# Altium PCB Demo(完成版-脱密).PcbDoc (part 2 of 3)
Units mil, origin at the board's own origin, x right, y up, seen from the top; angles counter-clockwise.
Board outline 2165.35 x 1574.8 mil, 6 copper layers (TOP, GND02, ART03, ART04, PWR05, BOTTOM); 172 components, 0 nets, 834 pads, 541 vias.
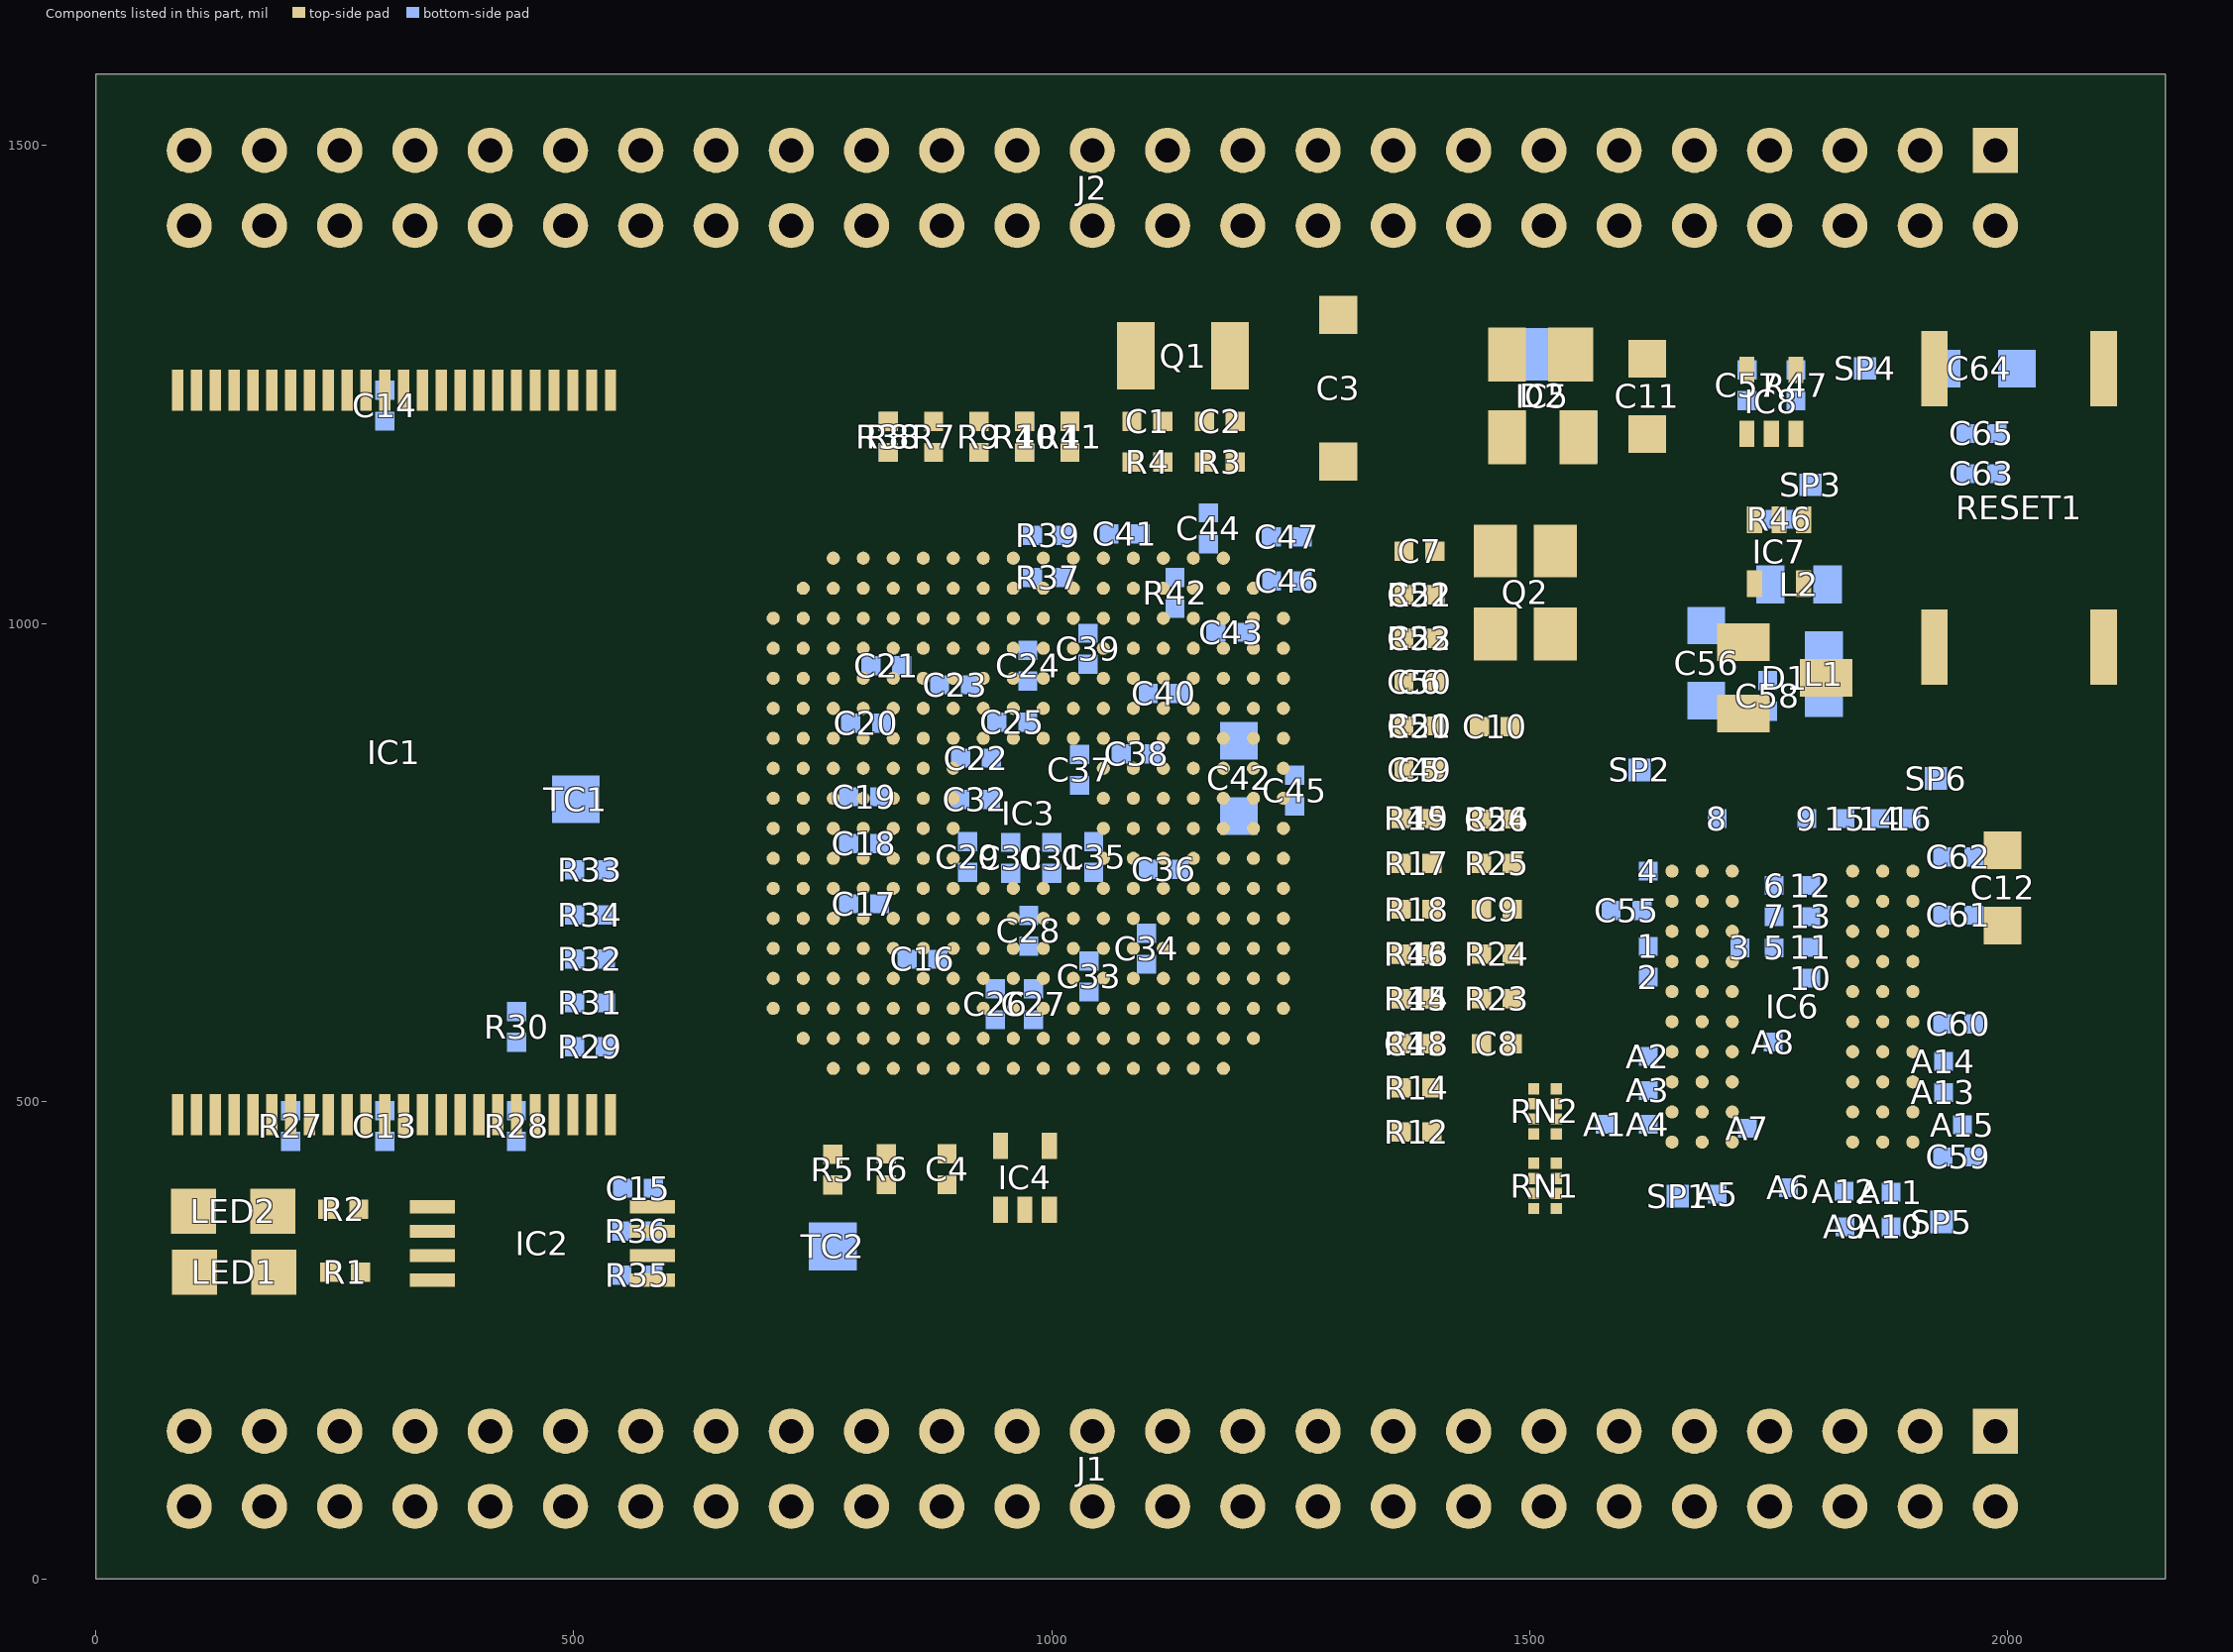
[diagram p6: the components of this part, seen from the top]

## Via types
v1: diameter 16, hole 8, TOP to BOTTOM, tented both sides, 541 vias

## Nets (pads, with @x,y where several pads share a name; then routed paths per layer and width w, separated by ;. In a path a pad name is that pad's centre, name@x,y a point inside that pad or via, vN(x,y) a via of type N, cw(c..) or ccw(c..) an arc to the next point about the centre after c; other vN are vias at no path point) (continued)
copper on no net: | length 160065.2
  TOP w5: v1(1330,664) 1337.48,671.48 1348.13,671.48 1365.56,654.06 ; v1(1330,693) 1330.48,693 1340,683.48 1348.13,683.48 1365.56,700.91 ; 1397.84,654.06 1412.79,669 v1(1423,669) ; v1(1423,700.91) 1449.56,700.91 1449.56,654.06 1449.56,607.2 1449.56,560.34
  TOP w5.7: v1(125.01,1073.73) 265.01,1073.73 400.58,1209.3 400.58,1243.94 ; v1(126.01,1120.73) 164.37,1159.09 164.37,1243.94 ; 184.05,1243.94 184.05,1204.92 v1(184.1,1204.87) ; 194,382 199,387 ; 196,326 201,321 ; v1(203.69,555.14) 223.42,535.41 223.42,486.07 ; 203.73,486.07 203.73,525.09 v1(203.78,525.14) ; 203.74,1243.94 203.74,1140 v1(223.01,1120.73) ; 223.42,1243.94 223.42,1204.92 v1(223.47,1204.87) ; 243.1,486.07 243.1,547.82 v1(285.01,589.73) ; v1(315.01,1084.87) 333.87,1103.73 352.01,1103.73 439.96,1191.68 439.96,1243.94 ; v1(316.01,1048.73) 459.64,1192.36 459.64,1243.94 ; v1(350.32,1124.87) 420.27,1194.82 420.27,1243.94 ; v1(365.01,525.73) 376.01,525.73 380.9,520.84 380.9,486.07 ; 400.58,486.07 v1(400.63,525.14) v1(400.63,525.14) ; v1(411.01,426.73) 420.27,435.99 420.27,486.07 ; 439.95,486.07 v1(440,525.14) v1(440,525.14) ; 582.31,312.82 820.69,312.82 v1@821.18,312.33 ; 582.31,338.41 v1(818.15,338.41) v1@818.24,338.5 ; 582.31,364 625.82,364 v1(626,364.18) ; v1(598.7,926.9) 614.4,942.6 708.6,942.6 ; v1(630.1,644.3) 692.9,644.3 708.6,660 ; v1(630.1,707.1) 645.8,722.8 708.6,722.8 ; v1(630.1,926.9) 692.9,926.9 708.6,911.2 ; v1(661.5,707.1) 724.3,707.1 740,722.8 ; v1(661.5,769.9) 692.9,801.3 755.7,801.3 771.4,785.6 ; v1(661.5,864.1) 677.2,879.8 708.6,879.8 ; v1@692.9,455.9 771.4,534.4 ; v1(692.9,581.5) 708.6,597.2 ; v1(692.9,612.9) 755.7,612.9 771.4,628.6 ; v1(692.9,675.7) 708.6,691.4 ; v1(692.9,769.9) 708.6,754.2 ; v1(692.9,864.1) 708.6,848.4 ; v1(692.9,989.7) 708.6,974 ; v1(692.9,1021.1) 708.6,1005.4 ; v1(724.3,455.9) 767.13,498.73 794.01,498.73 802.8,507.52 802.8,534.4 ; v1(724.3,518.7) 771.4,565.8 ; v1(724.3,581.5) 740,597.2 ; v1(724.3,675.7) 740,691.4 ; v1(724.3,738.5) 740,754.2 ; v1(724.3,769.9) 740,785.6 ; v1(724.3,832.7) 740,817 ; v1(724.3,864.1) 740,848.4 ; v1(724.3,958.3) 740,942.6 ; v1(724.3,989.7) 740,974 ; v1(724.3,1115.3) 724.3,1021.1 740,1005.4 ; v1(755.7,581.5) 771.4,597.2 ; v1(755.7,644.3) 771.4,660 ; v1(755.7,675.7) 771.4,691.4 ; v1(755.7,738.5) 771.4,754.2 ; v1(755.7,832.7) 771.4,817 ; v1(755.7,864.1) 771.4,848.4 ; v1(755.7,895.5) 771.4,879.8 ; v1(755.7,958.3) 771.4,942.6 ; v1(755.7,989.7) 771.4,974 ; v1(755.7,1021.1) 771.4,1005.4 ; v1(755.7,1115.3) 755.7,1052.5 771.4,1036.8 ; v1@755.7,1146.7 771.4,1131 771.4,1068.2 ; v1(771,385.74) 771,412.32 ; 771,444.6 v1(803.12,444.6) ; 771.4,911.2 v1(787.1,926.9) ; v1(787.1,518.7) 787.1,550.1 802.8,565.8 ; v1(787.1,581.5) 802.8,597.2 ; v1(787.1,612.9) 802.8,628.6 ; v1(787.1,644.3) 802.8,660 ; v1(787.1,675.7) 802.8,691.4 ; v1(787.1,738.5) 802.8,754.2 ; v1(787.1,864.1) 802.8,879.8 ; v1(787.1,1021.1) 802.8,1005.4 ; v1(787.1,1115.3) 787.1,1052.5 802.8,1036.8 ; v1(787.1,1151) 802.8,1135.3 802.8,1131 802.8,1068.2 ; 802.8,785.6 818.5,801.3 v1(849.9,801.3) ; v1(818.5,550.1) 834.2,565.8 ; v1(818.5,581.5) 834.2,597.2 ; v1(818.5,612.9) 834.2,628.6 ; v1(818.5,644.3) 834.2,660 ; v1(818.5,675.7) 834.2,691.4 ; v1(818.5,864.1) 834.2,848.4 ; v1(818.5,926.9) 834.2,911.2 ; v1(818.5,1021.1) 834.2,1005.4 ; v1(818.5,1052.5) 834.2,1036.8 ; v1(818.5,1083.9) 834.2,1068.2 ; 827,445 v1(827.01,476.73) ; v1(829,1151) 829,1179 ; 834.2,534.4 865.6,503 v1(897,503) ; v1(849.9,550.1) 865.6,565.8 ; v1(849.9,581.5) 865.6,597.2 ; v1(849.9,612.9) 865.6,628.6 ; v1(849.9,1021.1) 865.6,1005.4 ; v1(849.9,1052.5) 865.6,1036.8 ; v1(849.9,1083.9) 865.6,1068.2 ; 865.6,534.4 881.3,518.7 912.7,518.7 v1(928.4,503) ; v1(876.5,1151) 876.5,1179 ; 876.5,1211.28 v1(876.5,1239.28) ; v1(881.3,550.1) 897,565.8 ; v1(881.3,581.5) 897,597.2 ; v1(881.3,612.9) 897,628.6 ; v1(881.3,895.5) 897,911.2 ; v1(881.3,958.3) 897,942.6 ; v1(881.3,989.7) 897,974 ; v1(881.3,1021.1) 897,1005.4 ; v1(881.3,1115.3) 881.3,1083.9 897,1068.2 ; v1(912.7,550.1) 928.4,565.8 ; v1(912.7,581.5) 928.4,597.2 ; v1(912.7,612.9) 928.4,628.6 ; v1(912.7,958.3) 928.4,942.6 ; v1(912.7,989.7) 928.4,974 ; v1(912.7,1083.9) 912.7,1052.5 928.4,1036.8 ; v1(924,1115.3) 924,1104 928.4,1099.6 928.4,1068.2 ; v1@924,1151 v1(924,1154) 924,1179 ; 924,1211.28 v1(924,1239.28) ; v1(944.1,958.3) 959.8,942.6 ; v1(944.1,989.7) 959.8,974 ; v1(944.1,1021.1) 959.8,1005.4 ; v1(944.1,1052.5) 959.8,1036.8 ; v1(944.1,1083.9) 959.8,1068.2 ; v1@971.5,1151 v1(971.5,1154) 971.5,1179 ; 991.2,942.6 v1(1006.9,958.3) ; 991.2,974 v1(1006.9,989.7) ; 991.2,1005.4 v1(1006.9,1021.1) ; v1(1006.9,612.9) 1022.6,628.6 ; v1@1019,1151 v1(1019,1154) 1019,1179 ; 1022.6,597.2 v1(1038.3,581.5) ; 1054,534.4 v1(1069.7,518.7) ; 1054,565.8 v1(1069.7,550.1) ; 1054,597.2 v1(1069.7,581.5) ; 1054,628.6 v1(1069.7,612.9) ; 1054,942.6 1069.7,958.3 v1(1069.7,989.7) ; 1054,1005.4 v1(1069.7,1021.1) ; v1(1069.7,1052.5) 1085.4,1036.8 ; 1083.86,1169 1083.86,1211.28 1088.15,1215.58 1088.15,1280 1088.15,1263.15 ; 1085.4,534.4 v1(1101.1,518.7) ; 1085.4,565.8 v1(1101.1,550.1) ; 1085.4,597.2 v1(1101.1,581.5) ; 1085.4,628.6 v1(1101.1,612.9) ; 1085.4,942.6 v1(1101.1,958.3) ; 1085.4,1005.4 v1(1101.1,1021.1) ; 1116.14,1169 1130,1155.14 1130,1128 1101.1,1099.1 1101.1,1052.5 1116.8,1036.8 ; 1116.8,534.4 v1(1132.5,518.7) ; 1116.8,565.8 v1(1132.5,550.1) ; 1116.8,597.2 v1(1132.5,581.5) ; 1116.8,628.6 v1(1132.5,612.9) ; 1116.8,1005.4 1132.5,1021.1 1132.5,1081.5 1148,1097 1148,1157.14 1159.86,1169 ; v1(1132.5,675.7) 1148.2,691.4 ; 1148.2,534.4 v1(1163.9,518.7) ; 1148.2,565.8 v1(1163.9,550.1) ; 1148.2,597.2 v1(1163.9,581.5) ; 1148.2,628.6 v1(1163.9,612.9) ; 1148.2,660 v1(1163.9,644.3) ; 1148.2,722.8 v1(1163.9,707.1) ; 1148.2,754.2 v1(1163.9,738.5) ; 1148.2,785.6 1163.9,801.3 v1@1336.01,801.3 ; 1148.2,911.2 v1(1163.9,926.9) ; 1148.2,942.6 v1(1163.9,958.3) ; 1148.2,974 1163.9,989.7 1362.97,989.7 1368.5,984.17 ; v1(1163.9,675.7) 1179.6,660 ; 1179.6,565.8 v1(1195.3,550.1) ; 1179.6,597.2 v1(1195.3,612.9) ; 1179.6,691.4 v1(1195.3,675.7) ; 1179.6,722.8 v1(1195.3,707.1) ; 1179.6,754.2 v1(1195.3,738.5) ; 1179.6,942.6 v1(1195.3,926.9) ; 1179.6,1036.8 1200.8,1058 1251,1058 1305,1004 1342.6,1004 1368.5,1029.9 ; 1186.58,1280 1192.14,1274.44 1192.14,1211.28 1192.14,1169.23 ; 1192.14,1169 1192.14,1169.23 ; 1211.01,597.2 1220.54,597.2 1242.42,575.32 1242.42,488.58 1263.12,467.88 1365.56,467.88 ; 1211.01,628.6 v1(1226.71,612.9) ; 1211.01,660 v1(1226.71,644.3) ; 1211.01,691.4 v1(1226.71,675.7) ; 1211.01,722.8 v1(1226.71,707.1) ; 1211.01,754.2 v1(1226.71,738.5) ; 1211.01,974 v1(1226.71,958.3) ; 1211.01,1005.4 v1(1226.71,1021.1) ; v1(1226.98,770.18) 1242.4,785.6 1242.68,785.88 ; 1242.4,597.2 v1(1258.1,581.5) ; 1242.4,628.6 1288.14,628.6 1296.01,620.73 1296.01,593.73 1292.01,589.73 1284.01,589.73 1278.01,595.73 1278.01,605.73 1270.84,612.9 v1(1258.1,612.9) ; 1242.4,660 v1(1258.1,644.3) ; 1242.4,691.4 v1(1258.1,675.7) ; 1242.4,722.8 v1(1258.1,707.1) ; 1242.4,754.2 1276.55,720.05 1276.55,673.19 1315.01,634.73 1315.01,540.99 1342.12,513.88 1365.56,513.88 ; 1242.4,1005.4 v1(1258.1,1021.1) ; 1300,1169.23 1192.14,1169.23 ; v1(1339,893) 1339.28,892.72 1368.5,892.72 1368.5,847 ; 1365.56,560.34 1365.56,607.2 ; 1365.56,748.97 1365.56,795.83 ; 1397.84,467.88 1427.39,497.43 v1(1427.39,514.01) ; 1397.84,513.88 1397.84,560.34 v1(1397.84,583.73) ; 1397.84,607.2 v1(1420.88,630.24) ; 1397.84,700.91 v1(1423,700.91) ; 1397.84,748.97 v1(1424.01,748.97) 1447.82,748.97 ; 1397.84,795.83 1448.96,795.83 ; 1400.78,892.72 1446.83,892.72 1447.56,892 ; 1400.78,938.45 1400.78,985.78 1427,1012 1427,1022 1439,1034 1488,1034 1527,995 1527,989.01 ; 1400.78,1029.9 1400.78,1075.62 1464.01,1075.62 ; v1@1427.26,513.88 v1(1427.39,514.01) ; v1@1428.11,514.73 v1(1427.39,514.01) ; 1449.56,795.23 v1@1449.56,822.18 ; v1(1456.01,403.3) 1471.49,387.82 1504.34,387.82 ; v1(1456.01,434.79) 1471.49,419.31 1504.34,419.31 ; 1476.2,1281.31 1476.2,1320.2 1484,1328 v1(1514,1328) ; 1481.84,747.23 1481.84,748.97 1481.84,723.9 1486.01,719.73 1525.01,719.73 1535.01,709.73 1535.01,662.7 1530.59,658.28 1507.43,658.28 1503.01,653.86 1503.01,645.01 1507.43,640.58 1530.59,640.58 1535.01,636.16 1535.01,597.73 1547.01,585.73 1564.01,585.73 1574.01,595.73 1574.01,612.16 1569.59,616.58 1558.43,616.58 1554.01,621.01 1554.01,629.86 1558.43,634.28 1569.59,634.28 1574.01,638.7 1574.01,647.55 1569.59,651.98 1558.43,651.98 1554.01,656.41 1554.01,665.26 1558.43,669.68 1569.59,669.68 1574.01,674.11 1574.01,682.95 1569.59,687.38 1558.43,687.38 1554.01,691.8 1554.01,700.66 1558.43,705.08 1569.59,705.08 1574.01,709.51 1574.01,724.16 1569.59,728.58 1538.43,728.58 1534.01,733.01 1534.01,741.86 1538.43,746.28 1569.59,746.28 1574.01,750.7 1574.01,762.55 1569.59,766.98 ; 1481.84,795.23 1468.01,809.06 1468.01,837.73 1476.01,845.73 1502.03,845.73 1506.46,841.3 1506.46,804.16 1510.89,799.73 1519.74,799.73 1524.16,804.16 1524.16,841.3 1528.59,845.73 1541.01,845.73 1549.01,837.73 1549.01,817.73 1567.01,799.73 1567.01,792.73 1558.96,784.68 1508.43,784.68 1504.01,780.26 1504.01,771.41 1508.43,766.98 1569.59,766.98 ; v1(1484.01,403.3) 1484.28,403.57 1504.34,403.57 ; v1(1484.01,434.79) 1484.28,435.06 1504.34,435.06 ; v1(1484.01,468.01) 1484.01,489.73 1491.59,497.31 1504.34,497.31 ; v1@1484.28,513.06 1504.34,513.06 ; 1527.96,387.82 1560.81,387.82 v1(1576.29,403.3) ; 1527.96,403.57 v1@1548.02,403.57 ; 1527.96,419.31 1560.81,419.31 v1(1576.29,434.79) ; 1527.96,435.06 v1@1548.02,435.06 ; 1527.96,497.31 1580.59,497.31 1595.01,511.73 1595.01,548.84 v1(1576.29,567.56) ; 1527.96,513.06 1542.01,513.06 1548.02,519.07 1548.02,567.29 v1(1548.29,567.56) ; 1538.43,766.98 1569.59,766.98 ; v1(1566.01,822.73) 1587.01,801.73 1587.01,759.3 1591.43,754.88 1596.59,754.88 1601.01,750.45 1601.01,741.61 1596.59,737.18 1591.43,737.18 1587.01,732.76 1587.01,636.73 1626.01,597.73 1663.44,597.73 1680.51,614.8 ; 1649.01,488.82 v1(1664.76,473.07) ; 1649.01,520.32 1638.6,530.73 1627.01,530.73 1622.01,525.73 1622.01,507.73 1626.01,503.73 1663.92,503.73 v1(1664.76,504.57) ; 1649.01,551.81 v1(1664.76,536.06) ; v1(1664.76,630.55) 1680.51,646.3 ; 1680.51,457.32 v1(1696.26,441.57) ; 1680.51,488.82 v1(1696.26,473.07) ; 1680.51,520.32 v1(1696.26,504.57) ; 1680.51,551.81 v1(1696.26,536.06) ; 1680.51,583.31 v1(1696.26,567.56) ; 1680.51,677.8 1670.08,677.8 1664.01,671.73 1664.01,664.73 1668.01,660.73 1691.01,660.73 1696.26,665.98 v1(1696.26,693.54) ; 1680.51,709.29 v1(1696.26,725.03) ; 1680.51,740.79 1680.51,766.23 1673.01,773.73 1615.01,773.73 1609.01,779.73 1609.01,809.73 1616.01,816.73 1631.64,816.73 1636.06,812.3 1636.06,796.18 1640.49,791.76 1649.34,791.76 1653.76,796.18 1653.76,812.3 1658.18,816.73 1667.03,816.73 1671.46,812.3 1671.46,796.18 1675.89,791.76 1684.74,791.76 1689.16,796.18 1689.16,812.3 1693.59,816.73 1698.01,816.73 1704.01,816.73 1711.01,809.73 1711.01,771.29 v1(1696.26,756.53) ; 1712.01,457.32 1712.01,430.73 1706.01,424.73 1691.01,424.73 1684.01,417.73 1684.01,383.73 1689.01,378.73 1709.43,378.73 1713.86,383.16 1713.86,408.3 1718.28,412.73 1727.14,412.73 1731.56,408.3 1731.56,383.16 1735.99,378.73 1750.01,378.73 1754.01,382.73 1754.01,427.73 1740.17,441.57 v1(1727.76,441.57) ; 1712.01,488.82 1719.05,481.77 ; 1712.01,520.32 v1(1727.76,504.57) ; 1712.01,551.81 v1(1727.76,536.06) ; 1712.01,614.8 1712.01,604.73 1720.01,596.73 1745.01,596.73 1754.01,587.73 1754.01,580.73 1748.01,574.73 1734.01,574.73 1729.01,569.73 1729.01,560.73 1735.01,554.73 1770.01,554.73 1776.01,560.73 1776.01,604.73 1768.23,612.51 1745.79,612.51 v1(1727.76,630.54) ; 1712.01,646.3 1743.51,646.3 v1(1759.26,630.54) ; 1712.01,677.8 v1(1727.76,693.54) ; 1712.01,709.29 v1(1727.76,725.03) ; 1727.41,1198.53 1728.01,1197.93 v1(1728.01,1162.73) ; 1727.76,473.07 1719.05,481.77 ; v1@1734,1071.01 1734,1042.95 1735.41,1041.54 ; v1@1771.01,389.73 1771.01,429.82 1719.05,481.77 ; 1778.59,1265.46 1778.59,1298.59 v1(1779,1299) ; 1786.59,1108.47 v1(1857.01,1108.47) 1899.53,1108.47 1923.42,1084.58 1923.42,975.33 2100.58,975.33 ; v1(1790.74,756.53) 1804.01,743.27 1804.01,721.11 1799.59,716.68 1794.9,716.68 1790.48,712.26 1790.48,703.41 1794.9,698.98 1799.59,698.98 1804.01,694.55 1804.01,685.7 1799.59,681.28 1794.9,681.28 1790.48,676.86 1790.48,668.01 1794.9,663.58 1799.59,663.58 1804.01,659.16 1804.01,622.73 1811.94,614.8 1837.99,614.8 ; v1(1822.24,441.57) 1819.85,441.57 1806.01,427.73 1806.01,417.73 1815.01,408.73 1833.01,408.73 1837.99,413.71 1837.99,457.32 ; v1(1822.24,473.07) 1801.9,452.73 1787.01,452.73 1775.01,464.73 1775.01,482.73 1781.1,488.82 1837.99,488.82 ; v1(1822.24,504.57) 1837.99,520.32 ; v1(1822.24,536.06) 1837.99,551.81 ; v1(1822.24,662.04) 1837.99,646.3 ; v1(1822.24,693.54) 1837.99,677.8 ; v1(1822.24,725.03) 1837.99,709.29 ; v1(1853.74,441.57) 1869.49,457.32 ; v1(1853.74,473.07) 1869.49,488.82 ; v1(1853.74,504.57) 1869.49,520.32 ; v1(1853.74,536.06) 1869.49,551.81 ; v1(1853.74,567.56) 1869.49,583.31 ; v1(1853.74,630.54) 1869.49,614.8 ; v1(1853.74,662.04) 1869.49,646.3 ; v1(1853.74,693.54) 1869.49,677.8 ; v1(1853.74,725.03) 1869.49,709.29 ; 1869.49,740.79 v1(1885.24,725.04) ; v1(1885.23,504.57) 1900.98,520.32 ; v1(1885.23,536.06) 1900.98,551.81 ; 1900.98,488.82 v1(1916.73,473.07)
  TOP w10: v1@102,429 v1(102.32,428.68) 102.32,385 103.32,384 103.32,321 v1(103.32,272.68) v1@104,272 ; v1@274,357 v1(275,358) 275,387 ; v1(277,292) 277,321 ; v1(285,524.14) 297,524.14 302.16,518.98 302.16,486.07 ; 302.16,1243.94 302.16,1284.16 v1(303,1285) ; v1(302.43,426.14) 321.84,445.55 321.84,486.07 ; 321.84,1243.94 321.84,1273.84 v1(334,1286) ; 352,312.82 v1(394,312.82) 394,331.82 387.41,338.41 352,338.41 ; 352,364 v1(394,364) 394,383 387.41,389.59 352,389.59 ; 582.31,389.59 613.59,389.59 v1(626,402) ; v1(801,1211) 801.28,1211.28 829,1211.28 ; 827,412.72 v1(856.01,412.72) 890.49,412.72 892.5,414.73 991.01,414.73 997.59,408.15 997.59,386.53 ; 890.49,445 937.95,445 946.41,453.46 ; v1@972,1240 v1(971.5,1239.5) 971.5,1211.28 1019,1211.28 ; 1083.01,1091.73 1083.01,1125.99 v1(1055,1154) v1(1055,1270.73) 1055,1325 1069,1339 1210,1339 1223,1326 v1(1223,1271) v1(1223,1216) ; 1116.14,1211.28 1159.86,1211.28 ; 1116.8,1068.2 1116.8,1090.8 v1(1117,1091) ; 1148.2,1068.2 1165,1085 1165,1109 ; v1(1223,1196) v1(1223,1216) ; v1(1265,974) v1(1313,974) 1332.95,974 1368.5,938.45 1368.5,933.5 1385,917 1449,917 v1(1464.01,932.01) ; v1(1300,1279) 1300,1322.77 ; 1400.78,847 v1(1430,847) ; v1@1435,1194 v1(1435.69,1194.69) 1476.2,1194.69 ; 1464.01,989.01 v1(1464.01,932.01) ; v1(1476.89,1153.49) 1476.2,1154.18 1476.2,1194.69 ; 1479.84,892 v1(1512,892) ; 1481.84,560.34 1481.84,607.2 ; 1481.84,654.06 1481.84,700.91 1517.88,700.91 v1(1518.01,700.79) ; 1543.13,1281.31 1555,1293.18 v1(1555,1328) ; 1551,1194.69 1476.2,1194.69 ; 1648.41,614.2 1649.01,614.8 1630.94,614.8 1607.01,638.73 1607.01,698.79 1649.01,740.79 v1(1664.76,756.53) ; 1649.01,457.32 v1(1664.76,441.57) ; 1649.01,583.31 v1(1664.76,567.56) ; 1649.01,646.3 1634.44,646.3 1625.01,655.73 1625.01,684.73 1649.01,708.73 1649.01,709.29 v1(1664.76,725.03) ; 1649.01,677.8 v1(1664.76,693.54) ; 1712.01,740.79 v1(1727.76,756.53) ; 1727.41,1265.46 v1(1727.41,1298.41) v1@1728,1299 ; 1753,1198.53 1778.59,1198.53 v1(1811.53,1198.53) v1@1812,1199 ; 1761,1108.47 v1(1761,1145) ; v1(1822.24,756.53) 1837.99,740.79 ; v1(1885.23,473.06) 1900.98,457.32 ; v1(1885.23,567.56) 1900.98,583.31 ; v1(1885.23,630.54) 1900.98,614.8 ; v1(1885.23,662.04) 1900.98,646.3 ; v1(1885.23,693.54) 1900.98,677.8 ; v1(1885.23,756.53) 1900.98,740.79 ; 1900.98,709.29 v1(1916.73,725.03) ; 1923.42,1266.67 1961.67,1266.67 v1(1962,1267) ; 1165,1109 1202,1109 1236,1075 1261,1075 1308,1028 v1(1308,1026) 1337,1026 v1(1339,1028) v1(1339,1075.62) 1368.5,1075.62 1368.5,1104.5 v1(1392,1128) v1(1509,1128) 1527,1110 1527,1075.62 1527.38,1076 v1(1573,1076) 1573,958 1547.01,932.01 v1(1464.01,932.01) ; 1165,1109 1165,1131 v1(1174,1140) 1230,1140 1239,1131 1329,1131 1347,1149 1347,1195 v1(1326,1216) v1(1223,1216)
  TOP w12: 1085.4,879.8 v1(1101.1,895.5) 1085.4,911.2
  TOP w13.78: v1(849.9,707.1) 865.6,722.8 v1(849.9,738.5) 865.6,754.2 v1(849.9,769.9) 865.6,785.6 ; v1(849.9,895.5) 865.6,879.8 v1(849.9,864.1) 865.6,848.4 v1(849.9,832.7) 865.6,817 881.3,801.3 897,817 ; v1(849.9,926.9) 865.6,911.2 ; 865.6,660 v1(849.9,675.7) 865.6,691.4 ; v1(881.3,675.7) 897,660 912.7,644.3 928.4,660 ; v1(881.3,707.1) 897,722.8 ; v1(881.3,738.5) 897,754.2 ; v1(881.3,769.9) 897,785.6 ; v1(881.3,832.7) 897,848.4 ; 897,691.4 v1(912.7,675.7) 928.4,691.4 944.1,675.7 959.8,660 v1(944.1,644.3) ; 897,879.8 v1(912.7,895.5) 928.4,879.8 ; v1(912.7,707.1) 928.4,722.8 ; 928.4,911.2 v1(944.1,926.9) 959.8,911.2 ; v1(944.1,707.1) 959.8,722.8 ; 959.8,691.4 974.71,706.31 ; 959.8,879.8 v1(975.5,864.1) ; 991.2,660 v1(1006.9,644.3) 1022.6,660 ; 991.2,879.8 v1(1006.9,895.5) 991.2,911.2 v1(1006.9,926.9) 1022.6,942.6 ; 1022.6,722.8 v1(1038.3,707.1) ; 1022.6,879.8 v1(1038.3,895.5) 1054,911.2 v1(1069.7,926.9) ; 1022.6,911.2 v1(1038.3,926.9) ; 1054,660 v1(1069.7,644.3) 1085.4,660 ; 1054,722.8 v1(1069.7,707.1) ; 1054,754.2 v1(1069.7,738.5) ; 1054,817 v1(1069.7,801.3) 1054,785.6 v1(1069.7,769.9) ; 1054,848.4 v1(1069.7,832.7) ; 1054,879.8 v1(1069.7,895.5) ; v1(1069.7,675.7) 1054,691.4 v1(1038.3,675.7) 1022.6,691.4 ; 1085.4,691.4 v1(1101.1,707.1) ; 1085.4,722.8 v1(1069.7,738.5) ; 1085.4,785.6 v1(1101.1,769.9) 1085.4,754.2 v1(1069.7,738.5) ; 1085.4,817 v1(1101.1,832.7) 1085.4,848.4 ; 1085.4,974 v1(1101.1,989.7) ; 1116.8,754.2 v1(1132.5,769.9) 1116.8,785.6 ; 1116.8,817 v1(1132.5,832.7) 1116.8,848.4 ; 1116.8,942.6 v1(1132.5,958.3) ; 1116.8,974 v1(1132.5,989.7) ; 1148.2,1005.4 v1(1163.9,1021.1) ; 1148.2,1036.8 v1(1163.9,1052.5) ; 1179.6,974 v1(1195.3,958.3) ; 1179.6,1005.4 v1(1195.3,1021.1) ; 1179.6,1068.2 v1(1195.3,1083.9) ; 1481.84,607.2 1488.84,614.2 v1(1518.6,614.2) ; 1543.13,1281.31 1623.01,1281.31 1623.01,1277 ; 1995.01,683.99 2001.75,690.73 v1(2033.01,690.73) ; v1(1995.01,809.73) 1995.01,762.73 v1(2042.01,762.73) ; v1(2084.01,1333.73) 2100.58,1317.16 2100.58,1266.67 ; 974.71,706.31 991.2,722.8 v1(1006.9,707.1) 1022.6,691.4 ; 974.71,706.31 976.29,706.31 991.2,691.4 v1(1006.9,675.7) 1022.6,691.4 ; v1(1101.1,707.1) 1116.8,691.4 v1(1132.5,707.1) 1116.8,722.8 v1(1101.1,707.1)
  TOP w15: 199,387 242.72,387 ; 201,321 244.72,321 ; 1116.8,911.2 v1(1132.5,895.5)
  ART03 w6.2: 95.01,161.73 95.01,157.33 60.01,192.33 60.01,685.73 506.01,1131.73 828.01,1131.73 894.01,1065.73 925.93,1065.73 v1(944.1,1083.9) ; 176.34,76 138.01,114.33 138.01,195.73 78.01,255.73 78.01,681.73 495.88,1099.6 834.2,1099.6 v1(849.9,1083.9) ; 176.34,154.74 176.34,236.4 121.81,290.93 121.81,703.53 502.18,1083.9 v1(818.5,1083.9) ; v1(227.01,643.73) 227.01,627.73 235.01,619.73 235.01,333.99 v1(277,292) ; 254.01,80.73 254.01,77.07 215.01,116.07 215.01,165.73 215.01,230.73 136.98,308.76 136.98,691.24 513.94,1068.2 867.54,1068.2 883.24,1052.5 v1(944.1,1052.5) ; 255.08,154.74 255.08,186.73 255.08,213.66 153.21,315.53 153.21,684.51 521.2,1052.5 v1(818.5,1052.5) ; 333.82,76 298.01,111.81 298.01,197.73 168.98,326.76 168.98,674.78 530.93,1036.73 834.13,1036.73 v1(849.9,1052.5) ; 333.82,154.74 333.82,195.92 221.01,308.73 221.01,611.73 207.01,625.73 207.01,685.81 526.6,1005.4 865.6,1005.4 v1(881.3,1021.1) ; 412.56,76 373.01,115.55 373.01,224.73 250.01,347.73 250.01,705.73 518.28,974 897,974 v1(912.7,989.7) ; 412.56,154.74 412.56,221.18 300.01,333.73 300.01,361.73 265.98,395.76 265.98,698.89 524.82,957.73 671.01,957.73 689.01,939.73 737.13,939.73 v1(755.7,958.3) ; 468.01,649.73 460.93,656.81 ; 487.21,485.65 487.21,503.73 ; 487.21,704.73 487.21,698.73 ; 491.3,154.74 463.51,182.53 463.51,193.23 322.01,334.73 322.01,436.73 304.01,454.73 304.01,710.85 520.06,926.9 v1(598.7,926.9) ; 502.81,494.04 502.81,507.73 ; 502.81,698.73 502.81,692.73 ; 570.04,76 535.01,111.03 535.01,168.73 500.01,203.73 475.01,203.73 340.01,338.73 340.01,445.73 318.01,467.73 318.01,699.16 527.58,908.73 709.01,908.73 726.88,926.6 756.88,926.6 772.88,942.6 928.4,942.6 v1(944.1,958.3) ; 570.04,154.74 570.04,167.7 408.01,329.73 380.01,329.73 356.1,353.64 356.1,458.82 334.01,480.92 334.01,693.94 533.8,893.73 726.01,893.73 743.48,911.2 953.48,911.2 973.01,930.73 973.01,955.81 v1(1006.9,989.7) ; v1(630.1,644.3) 630.1,556.64 675.01,511.73 701.01,511.73 745.01,467.73 745.01,434.73 805.51,374.23 805.51,351.23 863.41,293.33 903.89,293.33 1042.48,154.74 ; v1(630.1,707.1) 598.48,707.1 565.21,673.83 565.21,517.53 667.01,415.73 667.01,399.73 870.01,196.73 894.01,196.73 917.01,173.73 917.01,119.73 928.01,108.73 982.01,108.73 1014.74,76 1042.48,76 ; 648.78,76 611.01,113.77 611.01,170.73 582.01,199.73 561.01,199.73 415.01,345.73 385.01,345.73 368.71,362.03 368.71,467.43 347.01,489.13 347.01,685.73 541.08,879.8 865.6,879.8 v1(881.3,895.5) ; 648.78,154.74 648.78,178.96 609.01,218.73 565.01,218.73 470.01,313.73 470.01,426.73 423.01,473.73 423.01,631.73 406.01,648.73 406.01,716.73 537.68,848.4 863.01,848.4 890.34,875.73 944.01,875.73 979.48,911.2 1014.07,911.2 1022.6,919.73 1022.6,1005.4 v1(1006.9,1021.1) ; v1(661.5,707.1) 644.13,689.73 602.85,689.73 580.81,667.69 580.81,519.93 684.01,416.73 684.01,405.73 876.01,213.73 904.75,213.73 930.01,188.47 930.01,132.73 941.01,121.73 992.01,121.73 1006.01,107.73 1060.01,107.73 1091.74,76 1121.22,76 ; v1(661.5,769.9) 567.18,769.9 502.81,705.53 502.81,692.73 ; v1(692.9,581.5) 708.6,597.2 794.54,597.2 802.8,588.94 802.8,523.94 866.01,460.73 866.01,426.73 877.01,415.73 877.01,390.73 1051.51,216.23 1063.01,216.23 ; v1(692.9,612.9) 674.01,594.01 674.01,566.73 690.01,550.73 745.01,550.73 771.01,524.73 771.01,507.73 838.01,440.73 838.01,403.73 1039.76,201.98 1073.98,201.98 1085.01,190.96 ; v1(692.9,675.7) 610.98,675.7 596.41,661.13 596.41,527.33 699.01,424.73 699.01,411.73 865.01,245.73 894.01,245.73 950.01,189.73 950.01,168.47 963.74,154.74 ; v1(692.9,769.9) 675.73,752.73 572.01,752.73 518.41,699.13 518.41,500.33 588.01,430.73 588.01,354.73 617.01,325.73 670.01,325.73 806.26,189.48 806.26,154.74 ; v1(724.3,675.7) 708.6,660 622.28,660 612.01,649.73 612.01,548.73 668.01,492.73 684.01,492.73 708.01,468.73 708.01,441.73 739.81,409.93 739.81,393.69 v1(821.41,312.1) 870.77,262.73 908.01,262.73 1004.01,166.73 1004.01,141.73 1025.01,120.73 1072.01,120.73 1084.01,108.73 1167.23,108.73 1199.96,76 ; v1(724.3,738.5) 708.53,722.73 592.01,722.73 549.61,680.33 549.61,512.13 649.01,412.73 649.01,395.73 885,159.74 885,154.74 ; v1(724.3,769.9) 708.47,785.73 563.01,785.73 487.21,709.93 487.21,698.73 ; v1(724.3,832.7) 547.48,832.7 424.04,709.26 424.04,658.73 456.01,626.76 456.01,464.73 484.01,436.73 484.01,326.73 575.01,235.73 633.01,235.73 690.01,178.73 690.01,113.51 727.52,76 ; 727.52,154.74 727.52,183.22 634.01,276.73 581.01,276.73 538.01,319.73 538.01,372.73 501.51,409.23 501.51,443.23 471.61,473.13 471.61,646.13 460.93,656.81 ; v1(755.7,644.3) 698.58,644.3 658.01,603.73 658.01,557.73 680.01,535.73 735.01,535.73 755.01,515.73 755.01,489.73 769.01,475.73 769.01,451.73 1033.01,187.73 1064.01,187.73 1080.01,171.73 1080.01,136.73 1095.01,121.73 1232.97,121.73 1278.7,76 ; v1(755.7,738.5) 740,754.2 709.48,754.2 693.01,737.73 586.01,737.73 534.01,685.73 534.01,503.73 605.01,432.73 605.01,358.73 621.01,342.73 678.01,342.73 827.01,193.73 827.01,181.73 843.01,165.73 843.01,130.73 861.01,112.73 893.01,112.73 929.74,76 963.74,76 ; v1(755.7,832.7) 736.73,813.73 555.34,813.73 443.01,701.4 443.01,674.73 460.93,656.81 ; v1(787.1,644.3) 802.8,628.6 859.14,628.6 865.6,622.14 865.6,510.73 905.01,471.32 905.01,408.73 1069.01,244.73 1236.01,244.73 1318.01,162.73 1318.01,115.43 1357.44,76 ; v1(787.1,675.7) 802.8,691.4 954.34,691.4 980.01,665.73 980.01,428.73 1107.01,301.73 1293.01,301.73 1339.01,255.73 1524.01,255.73 1575.01,204.73 1607.01,204.73 1639.01,172.73 1639.01,109.73 1672.4,76.34 1672.4,76 ; 806.26,76 760.01,122.25 760.01,186.73 653.01,293.73 597.01,293.73 555.01,335.73 555.01,378.73 521.01,412.73 521.01,446.65 487.21,480.45 487.21,503.73 ; v1(818.5,612.9) 834.2,597.2 834.2,514.54 890.01,458.73 890.01,400.73 1060.26,230.48 1096.01,230.48 ; v1(818.5,644.3) 903.44,644.3 951.01,596.73 951.01,415.73 1093.51,273.23 1149.01,273.23 ; v1(818.5,675.7) 835.47,658.73 907.01,658.73 965.01,600.73 965.01,422.73 1100.26,287.48 1285.26,287.48 1335.01,237.73 1511.01,237.73 1555.01,193.73 1555.01,114.65 1593.66,76 ; v1(876.5,1239.28) 876.5,1410.22 880.01,1413.73 ; v1(881.3,612.9) 897,597.2 897,539.73 912.7,524.03 912.7,489.04 939.01,462.73 939.01,399.73 1079.76,258.98 1253.2,258.98 1315.23,196.95 1393.97,196.95 1436.18,154.74 ; v1(881.3,1115.3) 858.01,1138.59 858.01,1372.73 841.01,1389.73 841.01,1451.01 885,1495 ; 885,76 861.8,99.2 841.54,99.2 825.01,115.73 788.01,115.73 773.01,130.73 773.01,196.73 659.01,310.73 605.01,310.73 571.01,344.73 571.01,390.73 534.01,427.73 534.01,456.04 502.81,487.24 502.81,507.73 ; v1(912.7,958.3) 928.4,974 955.28,974 982.01,1000.73 982.01,1108.73 954.01,1136.73 954.01,1174.73 996.01,1216.73 996.01,1321.73 1013.01,1338.73 1496.01,1338.73 1553.01,1395.73 1553.01,1457.73 1512.01,1498.73 ; v1(912.7,1083.9) 902.01,1094.59 902.01,1243.73 945.01,1286.73 945.01,1356.73 971.01,1382.73 1402.65,1382.73 1436.18,1416.26 ; v1(924,1239.28) 960.51,1275.79 960.51,1340.23 989.01,1368.73 1446.01,1368.73 1476.01,1398.73 1476.01,1453.73 1435.46,1494.28 ; v1(944.1,1021.1) 964.01,1041.01 964.01,1095.73 941.01,1118.73 941.01,1186.73 952.01,1197.73 952.01,1246.73 981.82,1276.54 981.82,1329.54 1005.01,1352.73 1451.39,1352.73 1514.92,1416.26 ; v1(971.5,1154) 1004.01,1121.49 1004.01,1056.73 1023.94,1036.8 1085.4,1036.8 v1(1101.1,1021.1) ; v1(1019,1154) 1019,1072.74 1039.24,1052.5 v1(1069.7,1052.5) ; v1(1069.7,581.5) 1052.01,563.81 1052.01,496.73 1089.74,459 1323.74,459 1336.28,446.46 1336.28,440.02 1325.75,429.49 1325.75,423.05 1332.18,416.62 1338.62,416.62 1349.15,427.15 1355.59,427.15 1362.02,420.72 1362.02,414.28 1351.49,403.75 1351.49,397.31 1357.92,390.88 1364.36,390.88 1374.89,401.41 1381.33,401.41 1387.76,394.98 1387.76,388.55 1377.22,378.01 1377.22,371.57 1383.66,365.14 1390.09,365.14 1400.63,375.68 1407.06,375.68 1426.01,356.73 1513.96,356.73 1518.51,352.18 1518.51,339.51 1523.06,334.96 1532.16,334.96 1536.71,339.51 1536.71,352.18 1541.26,356.73 1550.36,356.73 1554.91,352.18 1554.91,339.51 1559.46,334.96 1568.56,334.96 1573.11,339.51 1573.11,352.18 1577.66,356.73 1586.76,356.73 1591.31,352.18 1591.31,339.51 1595.86,334.96 1604.96,334.96 1609.51,339.51 1609.51,352.18 1614.06,356.73 1623.16,356.73 1627.71,352.18 1627.71,339.51 1632.26,334.96 1641.36,334.96 1645.91,339.51 1645.91,352.18 1650.46,356.73 1674.01,356.73 1696.26,378.98 1696.26,395.88 1700.81,400.43 1727.71,400.43 1732.26,404.98 1732.26,414.08 1727.71,418.63 1700.81,418.63 1696.26,423.18 v1(1696.26,441.57) ; 1078.23,197.73 1085.01,190.96 ; 1094.01,216.23 1063.01,216.23 ; v1(1101.1,550.1) 1085.4,534.4 1085.4,497.34 1105.01,477.73 1333.01,477.73 1345.32,465.42 1351.75,465.42 1365.64,479.31 1372.07,479.31 1378.51,472.87 1378.51,466.44 1364.62,452.55 1364.62,446.12 1371.06,439.68 1377.49,439.68 1391.38,453.57 1397.81,453.57 1404.24,447.13 1404.24,440.7 1390.36,426.82 1390.36,420.38 1396.79,413.95 1403.23,413.95 1417.11,427.83 1423.55,427.83 1429.98,421.4 1429.98,414.96 1416.1,401.08 1416.1,394.64 1432.01,378.73 1501.56,378.73 1506.11,383.28 1506.11,438.18 1510.66,442.73 1526.01,442.73 1532.01,436.73 1532.01,382.73 1536.01,378.73 1596.01,378.73 1604.01,386.73 1604.01,439.73 1610.01,445.73 1637.01,445.73 1642.01,440.73 1642.01,383.73 1646.01,379.73 1664.01,379.73 1680.51,396.23 1680.51,457.32 v1(1664.76,473.07) ; v1(1101.1,612.9) 1114,625.8 1114,653 1107,660 1055.28,660 1046.01,650.73 1046.01,604.73 1053.54,597.2 1205.54,597.2 1211.01,591.73 1211.01,566.73 1234.01,543.73 1309.01,543.73 1328.01,562.73 1450.01,562.73 1460.01,552.73 1511.01,552.73 1528.01,535.73 1640.6,535.73 1656.01,520.32 1749.16,520.32 1753.71,515.77 1753.71,486.87 1758.26,482.32 1767.36,482.32 1771.91,486.87 1771.91,515.77 1776.46,520.32 1793.42,520.32 1801.01,512.73 1801.01,468.73 1792.01,459.73 1738.01,459.73 1727.76,469.98 v1(1727.76,504.57) v1@1725.01,501.82 ; 1121.22,154.74 1085.01,190.96 ; 1126.01,230.48 1096.01,230.48 ; v1(1132.5,581.5) 1122.78,581.5 1116.8,575.52 1116.8,568.94 1120.01,565.73 1144.01,565.73 1148.2,561.54 1148.2,539.92 1142.68,534.4 1122.68,534.4 1116.8,528.52 1116.8,508.94 1128.01,497.73 1191.56,497.73 1196.11,502.28 1196.11,507.18 1200.66,511.73 1209.76,511.73 1214.31,507.18 1214.31,502.28 1218.86,497.73 1227.96,497.73 1232.51,502.28 1232.51,507.18 1237.06,511.73 1246.16,511.73 1250.71,507.18 1250.71,502.28 1255.26,497.73 1264.36,497.73 1268.91,502.28 1268.91,507.18 1273.46,511.73 1282.56,511.73 1287.11,507.18 1287.11,502.28 1291.66,497.73 1300.76,497.73 1305.31,502.28 1305.31,507.18 1309.86,511.73 1318.96,511.73 1323.51,507.18 1323.51,502.28 1328.06,497.73 1347.56,497.73 1352.11,502.28 1352.11,527.18 1356.66,531.73 1365.76,531.73 1370.31,527.18 1370.31,502.28 1374.86,497.73 1383.96,497.73 1388.51,502.28 1388.51,527.18 1393.06,531.73 1402.16,531.73 1406.71,527.18 1406.71,502.28 1411.26,497.73 1439.56,497.73 1444.11,502.28 1444.11,515.18 1448.66,519.73 1457.76,519.73 1462.31,515.18 1462.31,502.28 1466.86,497.73 1500.01,497.73 1508.92,488.82 1523.56,488.82 1528.11,493.37 1528.11,512.27 1532.66,516.82 1541.76,516.82 1546.31,512.27 1546.31,479.37 1550.86,474.82 1559.96,474.82 1564.01,478.87 1564.01,479.73 1564.51,480.23 1564.51,512.27 1569.06,516.82 1578.16,516.82 1582.71,512.27 1582.71,479.37 1587.26,474.82 1596.36,474.82 1600.91,479.37 1600.91,512.27 1605.46,516.82 1614.56,516.82 1619.11,512.27 1619.11,477.63 1626.01,470.73 1634.01,470.73 1652.1,488.82 1691.1,488.82 1696.26,493.98 v1(1696.26,504.57) ; v1(1163.9,581.5) 1179.6,565.8 1179.6,539.73 1191.6,527.73 1321.01,527.73 1341.01,547.73 1435.01,547.73 1446.01,536.73 1474.01,536.73 1484.01,526.73 v1(1484.01,514.01) ; v1(1163.9,675.7) 1148.2,691.4 1148.2,748.92 1187.61,788.33 1273.4,788.33 1280.73,781 1349.28,781 1367.01,798.73 1802.27,798.73 1853.74,747.26 v1(1853.74,725.03) ; v1(1163.9,707.1) 1179.6,722.8 1241.01,722.8 1254.94,736.73 1281.76,736.73 1286.31,732.18 1286.31,728.06 1290.86,723.51 1299.96,723.51 1304.51,728.06 1304.51,732.18 1309.06,736.73 1377.01,736.73 1383.01,742.73 1383.01,758.73 1389.01,764.73 1436.76,764.73 1441.31,760.18 1441.31,751.28 1445.86,746.73 1454.96,746.73 1459.51,751.28 1459.51,760.18 1464.06,764.73 1473.16,764.73 1477.71,760.18 1477.71,751.28 1482.26,746.73 1491.36,746.73 1495.91,751.28 1495.91,760.18 1500.46,764.73 1549.76,764.73 1554.31,760.18 1554.31,751.28 1558.86,746.73 1567.96,746.73 1572.51,751.28 1572.51,760.18 1577.06,764.73 1586.16,764.73 1590.71,760.18 1590.71,751.28 1595.26,746.73 1604.36,746.73 1608.91,751.28 1608.91,760.18 1613.46,764.73 1632.01,764.73 1655.95,740.79 1747.56,740.79 1752.11,745.34 1752.11,750.24 1756.66,754.79 1765.76,754.79 1770.31,750.24 1770.31,745.34 1774.86,740.79 1806.49,740.79 v1(1822.24,725.03) ; v1(1163.9,738.5) 1179.6,754.2 1348.48,754.2 1377.01,782.73 1784.01,782.73 1790.74,776 v1(1790.74,756.53) ; 1165.74,273.23 1149.01,273.23 ; v1(1195.3,675.7) 1211,691.4 1266.68,691.4 1279.01,703.73 1312.73,703.73 1325,716 1379.28,716 1391.01,727.73 1546.76,727.73 1551.31,723.18 1551.31,714.78 1555.86,710.23 1564.96,710.23 1569.51,714.78 1569.51,723.18 1574.06,727.73 1583.16,727.73 1587.71,723.18 1587.71,714.78 1592.26,710.23 1601.36,710.23 1605.91,714.78 1605.91,723.18 1610.46,727.73 1624.57,727.73 1643.01,709.29 1741.01,709.29 1754.45,722.73 1799.57,722.73 1813.01,709.29 1832.45,709.29 1837.99,703.75 1837.99,677.8 v1(1853.74,662.04) ; 1199.96,154.74 1138.47,216.23 1063.01,216.23 ; v1(1226.71,612.9) 1226.71,575.03 1240.01,561.73 1270.01,561.73 1289.01,580.73 1365.01,580.73 1387.01,602.73 1404,602.73 1409,597.73 1880.01,597.73 1900.98,618.7 1900.98,709.3 v1(1885.24,725.04) ; v1(1226.71,644.3) 1201.3,644.3 1185.6,628.6 1152.14,628.6 1143.01,637.73 1143.01,653.73 1149.28,660 1304,660 1326,638 1346,638 1393,685 1469,685 1476.2,677.8 1736.8,677.8 1752.54,693.54 v1(1822.24,693.54) ; v1(1258.1,581.5) 1256.32,579.73 1245.01,579.73 1241.01,583.73 1241.01,591.73 1245.01,595.73 1355.01,595.73 1379.6,620.32 1406.68,620.32 1416,611 1478,611 1497.73,630.73 1555.16,630.73 1559.71,626.18 1559.71,619.28 1564.26,614.73 1573.36,614.73 1577.91,619.28 1577.91,626.18 1582.46,630.73 1637.01,630.73 1654.01,613.73 1777.26,613.73 1782.26,618.73 1796.27,618.73 1804.27,610.73 1858.01,610.73 1869.49,622.21 1869.49,704.25 1865.01,708.73 1857.01,708.73 1853.74,705.46 v1(1853.74,693.54) ; v1@1259.92,614.73 v1(1258.1,612.9) 1247.1,612.9 1243,617 1243,622 1249,628 1268.92,628 1283.65,642.73 1292.75,642.73 1297.3,638.18 1297.3,613.7 1301,610 1348,610 1386,648 1433,648 1441,656 1441,666 1445,670 1456,670 1461,665 1461,653 1466,648 1473,648 1487.04,662.04 1752.55,662.04 ; 1278.7,165.04 1213.26,230.48 1096.01,230.48 ; v1(1420.88,630.24) 1477.24,630.24 1493.73,646.73 1787.27,646.73 1803.46,630.54 v1(1853.74,630.54) ; 1430.01,1499.73 1439.01,1499.73 1442.01,1496.73 ; v1@1483.4,513.4 v1@1484.01,512.79 ; 1514.92,76 1480.01,110.91 1480.01,179.73 1438.01,221.73 1328.01,221.73 1276.51,273.23 1149.01,273.23 ; v1(1548.29,567.56) 1564.46,583.73 1727.01,583.73 1755.76,583.73 1760.31,579.18 1760.31,567.57 1764.86,563.02 1773.96,563.02 1778.51,567.57 1778.51,579.18 1783.06,583.73 1792.16,583.73 1796.71,579.18 1796.71,567.57 1801.26,563.02 1810.36,563.02 1814.91,567.57 1814.91,579.18 1819.46,583.73 1824.01,583.73 1837.57,583.73 v1(1853.74,567.56) ; 1753,662.04 1752.55,662.04 ; v1(1779,1299) 1779.27,1298.73 1833.01,1298.73 1857.01,1274.73 v1(1857.01,1108.47) ; v1(1822.24,662.04) 1822.24,651.24 1818,647 1808,647 1792.96,662.04 1779.85,662.04 1775.3,666.59 1775.3,675.49 1770.75,680.04 1761.65,680.04 1757.1,675.49 1757.1,666.59 1752.55,662.04 ; 487.21,503.73 487.21,698.73 ; 502.81,507.73 502.81,692.73
  ART04 w5: 972,558.83 989.61,576.44 989.61,616.19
